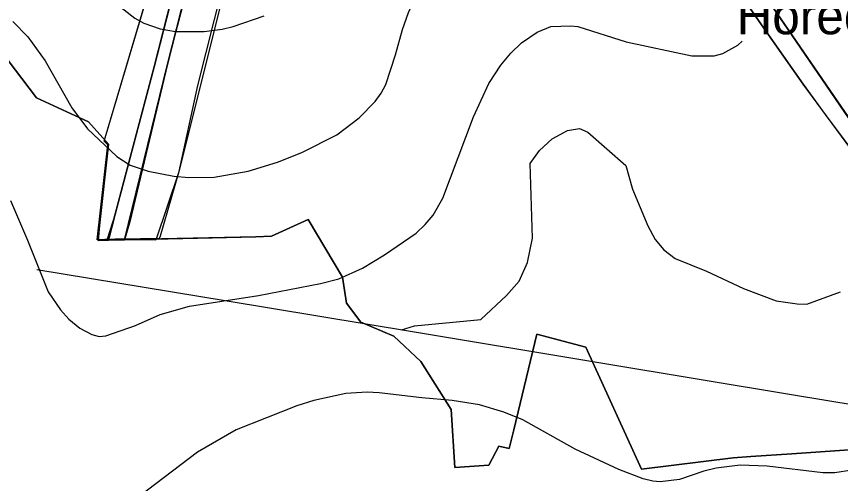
# Model space of a CAD drawing. Extents: x -662620 to -656370, y -1067090 to -1062990.
# Drawn here: x -661439.8 to -661050.3, y -1064074.2 to -1063853.7 of the extents above; entities that cross this region are included whole.
import ezdxf

# ---------------------------------------------------------------- set-up
doc = ezdxf.new("R2010")
doc.units = 0
for name, color, linetype in [('ELEK__VEDENÍ_VN_-_NADZEMNÍ', 7, 'Continuous'), ('HRANICE_KATASTRÁLNÍHO_ÚZEMÍ', 7, 'Continuous'), ('LOKÁLNÍ_BIOKORIDOR_-_NAVRŽENÝ', 7, 'Continuous'), ('MÍSTNÍ_NÁZVY', 7, 'Continuous'), ('OBVOD_PÚ', 7, 'Continuous'), ('ORNÁ_PŮDA_-_STÁVAJÍCÍ', 7, 'Continuous'), ('TRVALÝ_TRÁVNÍ_POROST_-_NAVRŽENÝ', 7, 'Continuous'), ('VODNÍ_PLOCHA_-_STÁVAJÍCÍ', 7, 'Continuous'), ('VRSTEVNICE_ZÁKLADNÍ', 7, 'Continuous')]:
    doc.layers.add(name, color=color, linetype=linetype)

msp = doc.modelspace()

# ---------------------------------------------------------------- linework, layer by layer
at = {"layer": 'ELEK__VEDENÍ_VN_-_NADZEMNÍ'}
msp.add_lwpolyline([(-661430.18, -1063973.15), (-661341.18, -1063987.78), (-661252.56, -1064002.41), (-661162.74, -1064017.32), (-661072.57, -1064032.36), (-660982.83, -1064047.06), (-660895.64, -1064061.52), (-660803.93, -1064076.92), (-660722.98, -1064090.23), (-660635.7, -1064104.5), (-660551.96, -1064118.27), (-660479.9, -1064130.34), (-660406.54, -1064193.02), (-660334.59, -1064253.68), (-660260.25, -1064316.77)], dxfattribs=at)
at = {"layer": 'HRANICE_KATASTRÁLNÍHO_ÚZEMÍ'}
msp.add_lwpolyline([(-661447.11, -1063869.86), (-661430.25, -1063892.05), (-661405.8, -1063903.48), (-661396.36, -1063913.97), (-661400.48, -1063952.31), (-661401.23, -1063959.39), (-661396.3, -1063959.29), (-661388.66, -1063959.12), (-661326.61, -1063957.7), (-661319.21, -1063957.4), (-661301.99, -1063949.5), (-661285.64, -1063976.79), (-661283.8, -1063989.04), (-661277.11, -1063997.98), (-661261.46, -1064004.57), (-661248.61, -1064016.6), (-661234.42, -1064039.19), (-661232.56, -1064066.61), (-661216.56, -1064065.56), (-661211.77, -1064056.54), (-661206.92, -1064057.64), (-661204.8, -1064048.9), (-661193.84, -1064003.66), (-661170.69, -1064009.78), (-661144.39, -1064067.49), (-661101.01, -1064062.09), (-661092.66, -1064061.51), (-661073.31, -1064060.21), (-661046.31, -1064058.36)], dxfattribs=at)
at = {"layer": 'LOKÁLNÍ_BIOKORIDOR_-_NAVRŽENÝ'}
for points in [[(-661395.21, -1063958.96), (-661395.24, -1063958.96), (-661395.26, -1063958.96), (-661395.28, -1063958.96), (-661401.66, -1063959.09), (-661396.63, -1063914.27), (-661398.32, -1063912.59), (-661350.52, -1063751.74)], [(-661342.36, -1063839.32), (-661354.22, -1063886.28), (-661363.23, -1063927.47), (-661371.9, -1063957.48), (-661372.38, -1063958.48), (-661390.08, -1063958.85), (-661390.17, -1063958.85), (-661390.19, -1063958.85), (-661390.21, -1063958.85), (-661390.35, -1063958.85), (-661390.37, -1063958.86), (-661390.39, -1063958.86), (-661390.4, -1063958.86), (-661390.44, -1063958.86), (-661390.46, -1063958.86), (-661390.48, -1063958.86), (-661390.5, -1063958.86), (-661390.51, -1063958.86), (-661390.56, -1063958.86), (-661390.58, -1063958.86), (-661390.61, -1063958.86), (-661390.68, -1063958.86), (-661390.84, -1063958.86), (-661390.87, -1063958.87), (-661390.92, -1063958.87), (-661392.38, -1063958.9), (-661392.43, -1063958.9), (-661392.45, -1063958.9), (-661392.48, -1063958.9), (-661392.49, -1063958.9), (-661392.5, -1063958.9), (-661392.52, -1063958.9), (-661392.59, -1063958.9), (-661392.61, -1063958.9), (-661392.62, -1063958.9), (-661392.64, -1063958.9), (-661392.68, -1063958.9), (-661392.74, -1063958.9), (-661392.76, -1063958.91), (-661392.79, -1063958.91), (-661392.8, -1063958.91), (-661392.87, -1063958.91), (-661393.18, -1063958.91), (-661393.2, -1063958.91), (-661393.21, -1063958.91), (-661393.28, -1063958.92), (-661393.3, -1063958.92), (-661393.31, -1063958.92), (-661393.34, -1063958.92), (-661393.35, -1063958.92), (-661393.37, -1063958.92), (-661393.38, -1063958.92), (-661393.4, -1063958.92), (-661393.43, -1063958.92), (-661393.45, -1063958.92), (-661393.47, -1063958.92), (-661393.49, -1063958.92), (-661393.53, -1063958.92), (-661393.55, -1063958.92), (-661393.58, -1063958.92), (-661393.6, -1063958.92), (-661393.62, -1063958.92), (-661393.65, -1063958.92), (-661393.67, -1063958.92), (-661393.68, -1063958.92), (-661393.69, -1063958.92), (-661393.79, -1063958.93), (-661393.83, -1063958.93), (-661393.84, -1063958.93), (-661393.87, -1063958.93), (-661393.89, -1063958.93), (-661393.92, -1063958.93), (-661393.96, -1063958.93), (-661393.97, -1063958.93), (-661394.01, -1063958.93), (-661394.05, -1063958.93), (-661394.1, -1063958.93), (-661394.77, -1063958.95), (-661394.8, -1063958.95), (-661394.82, -1063958.95), (-661394.83, -1063958.95), (-661394.84, -1063958.95), (-661394.85, -1063958.95), (-661394.86, -1063958.95), (-661394.87, -1063958.95), (-661394.89, -1063958.95), (-661395.03, -1063958.95), (-661395.13, -1063958.96), (-661395.15, -1063958.96), (-661395.17, -1063958.96), (-661395.18, -1063958.96), (-661395.21, -1063958.96)]]:
    msp.add_lwpolyline(points, dxfattribs=at)
at = {"layer": 'OBVOD_PÚ'}
for points in [[(-661447.11, -1063869.86), (-661430.25, -1063892.05)], [(-661430.25, -1063892.05), (-661405.8, -1063903.48)], [(-661405.8, -1063903.48), (-661396.36, -1063913.97)], [(-661396.36, -1063913.97), (-661400.48, -1063952.31)], [(-661319.21, -1063957.4), (-661301.99, -1063949.5)], [(-661301.99, -1063949.5), (-661285.64, -1063976.79)], [(-661400.48, -1063952.31), (-661401.23, -1063959.39)], [(-661396.3, -1063959.29), (-661388.66, -1063959.12)], [(-661388.66, -1063959.12), (-661326.61, -1063957.7)], [(-661326.61, -1063957.7), (-661319.21, -1063957.4)], [(-661401.23, -1063959.39), (-661396.3, -1063959.29)], [(-661285.64, -1063976.79), (-661283.8, -1063989.04)], [(-661283.8, -1063989.04), (-661277.11, -1063997.98)], [(-661277.11, -1063997.98), (-661261.46, -1064004.57)], [(-661261.46, -1064004.57), (-661248.61, -1064016.6)], [(-661204.8, -1064048.9), (-661193.84, -1064003.66)], [(-661193.84, -1064003.66), (-661170.69, -1064009.78)], [(-661170.69, -1064009.78), (-661144.39, -1064067.49)], [(-661248.61, -1064016.6), (-661234.42, -1064039.19)], [(-661234.42, -1064039.19), (-661232.56, -1064066.61)], [(-661206.92, -1064057.64), (-661204.8, -1064048.9)], [(-661216.56, -1064065.56), (-661211.77, -1064056.54)], [(-661211.77, -1064056.54), (-661206.92, -1064057.64)], [(-661092.66, -1064061.51), (-661073.31, -1064060.21)], [(-661073.31, -1064060.21), (-661046.31, -1064058.36)], [(-661144.39, -1064067.49), (-661101.01, -1064062.09)], [(-661101.01, -1064062.09), (-661092.66, -1064061.51)], [(-661232.56, -1064066.61), (-661216.56, -1064065.56)]]:
    msp.add_lwpolyline(points, dxfattribs=at)
at = {"layer": 'ORNÁ_PŮDA_-_STÁVAJÍCÍ'}
for p, q in [((-661368.35, -1063876.17), (-661351.05, -1063808.06)), ((-661113.87, -1063819.66), (-661086.58, -1063859.15)), ((-661030.47, -1063924.95), (-661091.33, -1063836.14)), ((-661366.05, -1063843.69), (-661374.7, -1063877.52)), ((-661086.58, -1063859.15), (-661086.57, -1063859.16)), ((-661086.57, -1063859.16), (-661068.05, -1063885.61)), ((-661430.25, -1063892.05), (-661447.11, -1063869.86)), ((-661372.56, -1063893.63), (-661368.35, -1063876.17)), ((-661374.7, -1063877.52), (-661393.15, -1063946.95)), ((-661068.05, -1063885.61), (-661057.55, -1063900.03)), ((-661405.8, -1063903.48), (-661430.25, -1063892.05)), ((-661373.97, -1063899.6), (-661372.56, -1063893.63)), ((-661378, -1063916.8), (-661373.97, -1063899.6)), ((-661057.55, -1063900.03), (-661045.47, -1063916.26)), ((-661396.36, -1063913.97), (-661405.8, -1063903.48)), ((-661400.48, -1063952.31), (-661396.36, -1063913.97)), ((-661381.22, -1063930.24), (-661378, -1063916.8)), ((-661386.28, -1063950.59), (-661381.22, -1063930.24)), ((-661393.15, -1063946.95), (-661396.3, -1063959.29)), ((-661388.68, -1063959.12), (-661386.28, -1063950.59)), ((-661301.99, -1063949.5), (-661319.21, -1063957.4)), ((-661285.64, -1063976.79), (-661301.99, -1063949.5)), ((-661401.23, -1063959.39), (-661400.48, -1063952.31)), ((-661388.66, -1063959.12), (-661388.68, -1063959.12)), ((-661386.11, -1063959.06), (-661388.66, -1063959.12)), ((-661326.61, -1063957.7), (-661386.11, -1063959.06)), ((-661319.21, -1063957.4), (-661326.61, -1063957.7)), ((-661396.3, -1063959.29), (-661401.23, -1063959.39)), ((-661283.8, -1063989.04), (-661285.64, -1063976.79)), ((-661277.11, -1063997.98), (-661283.8, -1063989.04)), ((-661261.46, -1064004.57), (-661277.11, -1063997.98)), ((-661248.61, -1064016.6), (-661261.46, -1064004.57)), ((-661193.84, -1064003.66), (-661204.8, -1064048.9)), ((-661170.69, -1064009.78), (-661193.84, -1064003.66)), ((-661144.39, -1064067.49), (-661170.69, -1064009.78)), ((-661234.42, -1064039.19), (-661248.61, -1064016.6)), ((-661232.56, -1064066.61), (-661234.42, -1064039.19)), ((-661204.8, -1064048.9), (-661206.92, -1064057.64)), ((-661211.77, -1064056.54), (-661216.56, -1064065.56)), ((-661206.92, -1064057.64), (-661211.77, -1064056.54)), ((-661073.31, -1064060.21), (-661092.66, -1064061.51)), ((-661046.31, -1064058.36), (-661073.31, -1064060.21)), ((-661101.01, -1064062.09), (-661144.39, -1064067.49)), ((-661092.66, -1064061.51), (-661101.01, -1064062.09)), ((-661216.56, -1064065.56), (-661232.56, -1064066.61))]:
    msp.add_line(p, q, dxfattribs=at)
for points in [[(-661442.78, -1063676.79), (-661425.23, -1063669.79), (-661400.94, -1063657.93), (-661369.19, -1063641.54), (-661353.29, -1063632.95), (-661331.82, -1063648.37), (-661324.97, -1063663.2), (-661323.5, -1063671.14), (-661324.61, -1063681.33), (-661329.81, -1063701.13), (-661340.02, -1063743.77), (-661351.88, -1063789.7), (-661362.44, -1063829.13), (-661366.05, -1063843.69), (-661374.7, -1063877.52), (-661393.15, -1063946.95), (-661396.3, -1063959.29), (-661401.23, -1063959.39), (-661400.48, -1063952.31), (-661396.36, -1063913.97), (-661405.8, -1063903.48), (-661430.25, -1063892.05), (-661447.11, -1063869.86)], [(-661046.31, -1064058.36), (-661073.31, -1064060.21), (-661092.66, -1064061.51), (-661101.01, -1064062.09), (-661144.39, -1064067.49), (-661170.69, -1064009.78), (-661193.84, -1064003.66), (-661204.8, -1064048.9), (-661206.92, -1064057.64), (-661211.77, -1064056.54), (-661216.56, -1064065.56), (-661232.56, -1064066.61), (-661234.42, -1064039.19), (-661248.61, -1064016.6), (-661261.46, -1064004.57), (-661277.11, -1063997.98), (-661283.8, -1063989.04), (-661285.64, -1063976.79), (-661301.99, -1063949.5), (-661319.21, -1063957.4), (-661326.61, -1063957.7), (-661386.11, -1063959.06), (-661388.66, -1063959.12), (-661388.68, -1063959.12), (-661386.28, -1063950.59), (-661381.22, -1063930.24), (-661378, -1063916.8), (-661373.97, -1063899.6), (-661372.56, -1063893.63), (-661368.35, -1063876.17), (-661351.05, -1063808.06)], [(-661113.87, -1063819.66), (-661086.58, -1063859.15), (-661086.57, -1063859.16), (-661068.05, -1063885.61), (-661057.55, -1063900.03), (-661045.47, -1063916.26)], [(-661030.47, -1063924.95), (-661091.33, -1063836.14)]]:
    msp.add_lwpolyline(points, dxfattribs=at)
at = {"layer": 'TRVALÝ_TRÁVNÍ_POROST_-_NAVRŽENÝ'}
for points in [[(-661357.93, -1063640.17), (-661361.61, -1063637.03), (-661353.29, -1063632.95), (-661331.82, -1063648.37), (-661324.97, -1063663.2), (-661323.5, -1063671.14), (-661324.61, -1063681.33), (-661329.81, -1063701.13), (-661340.02, -1063743.77), (-661351.88, -1063789.7), (-661362.44, -1063829.13), (-661366.05, -1063843.69), (-661374.7, -1063877.52), (-661393.15, -1063946.95), (-661396.89, -1063958.85), (-661401.23, -1063959.39), (-661400.48, -1063952.31), (-661396.63, -1063914.27), (-661398.32, -1063912.59), (-661350.44, -1063751.3), (-661342.8, -1063718.06), (-661335.43, -1063684.45), (-661333.51, -1063671.24), (-661335.99, -1063661.26)], [(-661326.66, -1063651.09), (-661320.33, -1063655.97), (-661309.24, -1063663.96), (-661300.32, -1063670.4), (-661302.75, -1063682.09), (-661313.86, -1063730.62), (-661363.23, -1063927.47), (-661373.85, -1063959.23), (-661388.66, -1063959.12), (-661368.35, -1063876.18), (-661341.86, -1063775.07), (-661328.1, -1063715.89), (-661317.27, -1063672.85), (-661317.33, -1063667.96), (-661323.5, -1063656.55)]]:
    msp.add_lwpolyline(points, close=True, dxfattribs=at)
at = {"layer": 'VODNÍ_PLOCHA_-_STÁVAJÍCÍ'}
for p, q in [((-661351.05, -1063808.06), (-661368.35, -1063876.18)), ((-661086.58, -1063859.15), (-661113.88, -1063819.66)), ((-661091.33, -1063836.14), (-661030.42, -1063925.02)), ((-661374.7, -1063877.52), (-661366.05, -1063843.69)), ((-661068.05, -1063885.61), (-661086.58, -1063859.15)), ((-661368.35, -1063876.18), (-661386.28, -1063950.59)), ((-661393.15, -1063946.95), (-661374.7, -1063877.52)), ((-661045.47, -1063916.26), (-661068.05, -1063885.61)), ((-661396.3, -1063959.29), (-661393.15, -1063946.95)), ((-661386.28, -1063950.59), (-661388.68, -1063959.12)), ((-661388.68, -1063959.12), (-661396.3, -1063959.29))]:
    msp.add_line(p, q, dxfattribs=at)
msp.add_lwpolyline([(-661386.28, -1063950.59), (-661388.68, -1063959.12), (-661396.3, -1063959.29), (-661393.15, -1063946.95), (-661374.7, -1063877.52), (-661366.05, -1063843.69), (-661362.44, -1063829.13), (-661351.88, -1063789.7), (-661340.02, -1063743.77), (-661329.81, -1063701.13), (-661324.61, -1063681.33), (-661323.5, -1063671.14), (-661324.97, -1063663.2), (-661331.82, -1063648.37), (-661326.67, -1063651.09), (-661323.5, -1063656.55), (-661317.33, -1063667.96), (-661317.27, -1063672.85), (-661328.1, -1063715.89), (-661334.65, -1063743.77), (-661351.05, -1063808.06), (-661368.35, -1063876.18)], close=True, dxfattribs=at)
for points in [[(-661045.47, -1063916.26), (-661068.05, -1063885.61), (-661086.58, -1063859.15), (-661113.88, -1063819.66)], [(-661091.33, -1063836.14), (-661030.42, -1063925.02)]]:
    msp.add_lwpolyline(points, dxfattribs=at)
at = {"layer": 'VRSTEVNICE_ZÁKLADNÍ'}
for points in [[(-661277.76, -1063901.51), (-661270.3, -1063893.91), (-661267.44, -1063889.9), (-661265.29, -1063885.88), (-661260.7, -1063871.83), (-661257.4, -1063859.79), (-661254.54, -1063851.77), (-661245.07, -1063831.7), (-661237.05, -1063819.37), (-661233.89, -1063812.49), (-661231.74, -1063803.88), (-661231.46, -1063781.52), (-661227.16, -1063752.28), (-661223.86, -1063741.96), (-661222.42, -1063733.5)], [(-661277.76, -1063901.51), (-661270.3, -1063893.91), (-661267.44, -1063889.9), (-661265.29, -1063885.88), (-661260.7, -1063871.83), (-661257.4, -1063859.79), (-661254.54, -1063851.77), (-661245.07, -1063831.7), (-661237.05, -1063819.37), (-661233.89, -1063812.49), (-661231.74, -1063803.88), (-661231.46, -1063781.52), (-661227.16, -1063752.28), (-661223.86, -1063741.96), (-661222.42, -1063733.5)], [(-661392.59, -1063847.75), (-661383.84, -1063854.49), (-661379.54, -1063856.78), (-661371.8, -1063859.51), (-661364.63, -1063860.8), (-661351.16, -1063860.8)], [(-661392.59, -1063847.75), (-661383.84, -1063854.49), (-661379.54, -1063856.78), (-661371.8, -1063859.51), (-661364.63, -1063860.8), (-661351.16, -1063860.8)], [(-661351.16, -1063860.8), (-661342.56, -1063859.65), (-661337.39, -1063858.36), (-661322.69, -1063853.46)], [(-661351.16, -1063860.8), (-661342.56, -1063859.65), (-661337.39, -1063858.36), (-661322.69, -1063853.46)], [(-661441.47, -1063856.07), (-661434.45, -1063863.38), (-661426.27, -1063874.7), (-661413.66, -1063896.78), (-661406.2, -1063906.81), (-661392.3, -1063919.86), (-661386.13, -1063923.87), (-661377.53, -1063926.74), (-661365.49, -1063929.03), (-661358.32, -1063929.75), (-661346.28, -1063929.61), (-661330.23, -1063926.74), (-661316.47, -1063922.44), (-661305, -1063917.99), (-661288.37, -1063909.54), (-661277.76, -1063901.51)], [(-661441.47, -1063856.07), (-661434.45, -1063863.38), (-661426.27, -1063874.7), (-661413.66, -1063896.78), (-661406.2, -1063906.81), (-661392.3, -1063919.86), (-661386.13, -1063923.87), (-661377.53, -1063926.74), (-661365.49, -1063929.03), (-661358.32, -1063929.75), (-661346.28, -1063929.61), (-661330.23, -1063926.74), (-661316.47, -1063922.44), (-661305, -1063917.99), (-661288.37, -1063909.54), (-661277.76, -1063901.51)], [(-661442.62, -1063940.64), (-661434.59, -1063959.28), (-661424.84, -1063983.65), (-661418.96, -1063992.25), (-661415.09, -1063996.55), (-661409.79, -1064000.85), (-661404.2, -1064003.86), (-661400.76, -1064004.72), (-661397.6, -1064004.44), (-661383.55, -1063999.56), (-661371.8, -1063994.4), (-661358.04, -1063990.39), (-661325.35, -1063985.37), (-661296.11, -1063979.78), (-661287.51, -1063977.49), (-661276.33, -1063972.47), (-661265.86, -1063966.3), (-661250.95, -1063955.98), (-661246.65, -1063951.97), (-661242.92, -1063947.53), (-661238.34, -1063939.5), (-661223.72, -1063901.08), (-661216.55, -1063885.31), (-661210.81, -1063876.71), (-661206.23, -1063870.97), (-661201.06, -1063866.1), (-661193.75, -1063861.08), (-661187.28, -1063858.45), (-661177.84, -1063858.07), (-661174.54, -1063858.5), (-661151.61, -1063865.67), (-661120.64, -1063872.26), (-661110.04, -1063872.26), (-661106.02, -1063871.12), (-661098.85, -1063867.25), (-661096.85, -1063865.38)], [(-661442.62, -1063940.64), (-661434.59, -1063959.28), (-661424.84, -1063983.65), (-661418.96, -1063992.25), (-661415.09, -1063996.55), (-661409.79, -1064000.85), (-661404.2, -1064003.86), (-661400.76, -1064004.72), (-661397.6, -1064004.44), (-661383.55, -1063999.56), (-661371.8, -1063994.4), (-661358.04, -1063990.39), (-661325.35, -1063985.37), (-661296.11, -1063979.78), (-661287.51, -1063977.49), (-661276.33, -1063972.47), (-661265.86, -1063966.3), (-661250.95, -1063955.98), (-661246.65, -1063951.97), (-661242.92, -1063947.53), (-661238.34, -1063939.5), (-661223.72, -1063901.08), (-661216.55, -1063885.31), (-661210.81, -1063876.71), (-661206.23, -1063870.97), (-661201.06, -1063866.1), (-661193.75, -1063861.08), (-661187.28, -1063858.45), (-661177.84, -1063858.07), (-661174.54, -1063858.5), (-661151.61, -1063865.67), (-661120.64, -1063872.26), (-661110.04, -1063872.26), (-661106.02, -1063871.12), (-661098.85, -1063867.25), (-661096.85, -1063865.38)], [(-661257.78, -1064001.65), (-661251.71, -1063999.73), (-661220.41, -1063996.77), (-661208.19, -1063985.44), (-661202.2, -1063978.67), (-661198.35, -1063969.86), (-661195.98, -1063958.35), (-661196.94, -1063923.12), (-661192.58, -1063916.9), (-661186.65, -1063911.39), (-661179.33, -1063907.46), (-661173.63, -1063906.54), (-661169.7, -1063908.39), (-661151.79, -1063924.04), (-661148.61, -1063935.29), (-661141.43, -1063952.58), (-661137.95, -1063958.98), (-661133.81, -1063963.79), (-661128.56, -1063968.01), (-661113.75, -1063973.97), (-661096.21, -1063982.15), (-661080.82, -1063987.96), (-661070.9, -1063989.33), (-661066.31, -1063989.48), (-661050.33, -1063983.74)], [(-661044.95, -1064067.94), (-661052.98, -1064069.23), (-661058.71, -1064069.09), (-661085.09, -1064066.08), (-661097.71, -1064065.51), (-661109.17, -1064066.94), (-661114.91, -1064068.37), (-661126.38, -1064072.24), (-661135.55, -1064073.39), (-661138.99, -1064073.1), (-661143.58, -1064071.96), (-661155.05, -1064067.66), (-661175.69, -1064057.91), (-661200.49, -1064044.15), (-661209.52, -1064040.56), (-661220.99, -1064037.12), (-661233.89, -1064034.97), (-661248.23, -1064033.82), (-661268.3, -1064031.39), (-661274.03, -1064031.1), (-661284.07, -1064031.67), (-661299.26, -1064034.97), (-661307.29, -1064037.55), (-661335.96, -1064048.88), (-661354.31, -1064059.34), (-661381.83, -1064080.31)], [(-661044.95, -1064067.94), (-661052.98, -1064069.23), (-661058.71, -1064069.09), (-661085.09, -1064066.08), (-661097.71, -1064065.51), (-661109.17, -1064066.94), (-661114.91, -1064068.37), (-661126.38, -1064072.24), (-661135.55, -1064073.39), (-661138.99, -1064073.1), (-661143.58, -1064071.96), (-661155.05, -1064067.66), (-661175.69, -1064057.91), (-661200.49, -1064044.15), (-661209.52, -1064040.56), (-661220.99, -1064037.12), (-661233.89, -1064034.97), (-661248.23, -1064033.82), (-661268.3, -1064031.39), (-661274.03, -1064031.1), (-661284.07, -1064031.67), (-661299.26, -1064034.97), (-661307.29, -1064037.55), (-661335.96, -1064048.88), (-661354.31, -1064059.34), (-661381.83, -1064080.31)]]:
    msp.add_lwpolyline(points, dxfattribs=at)

# ---------------------------------------------------------------- texts
at = {"layer": 'MÍSTNÍ_NÁZVY'}
msp.add_text('Horecký', height=17.5, dxfattribs=at).set_placement((-661099.5, -1063862.1))

doc.saveas('drawing.dxf')
